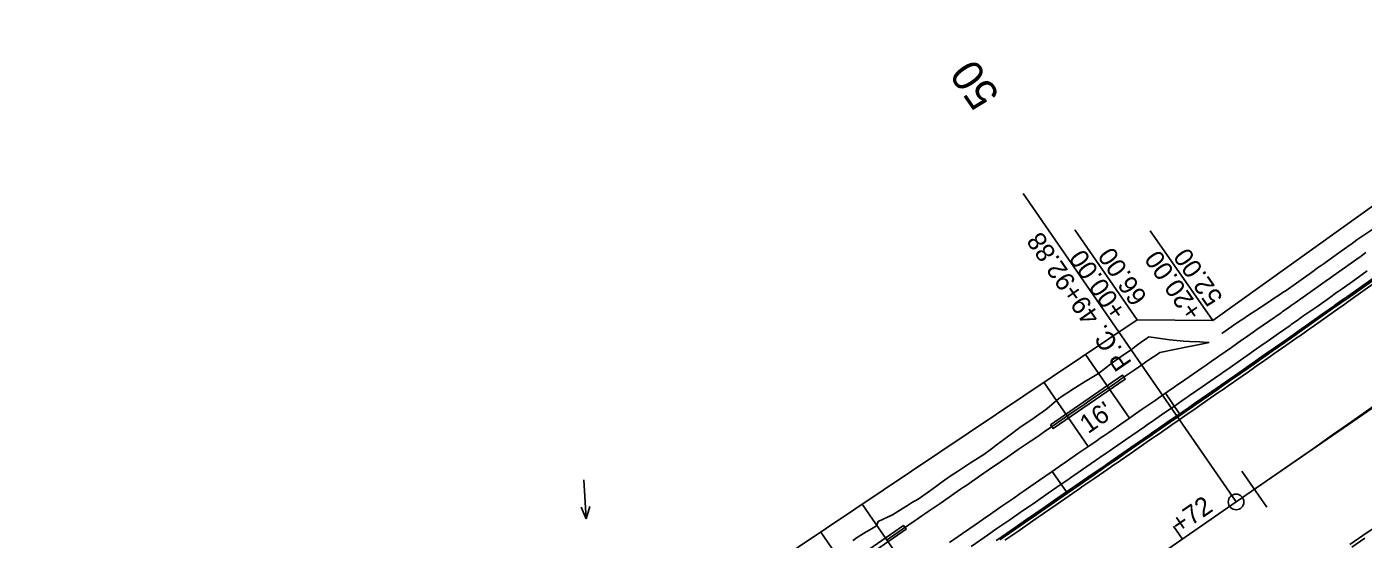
# Model space of a CAD drawing. Extents: x 1147550 to 1149124, y 2017436 to 2018779.
# Drawn here: x 1147906 to 1148333.9, y 2018014.6 to 2018178.7 of the extents above; entities that cross this region are included whole.
import ezdxf

# ---------------------------------------------------------------- set-up
doc = ezdxf.new("R2010")
doc.units = 0
for name, color, linetype in [('S_EDGE_CONCRETE', 7, 'Continuous'), ('S_ELECTRIC_UTILITIES', 7, 'Continuous'), ('S_HEADWALL', 7, 'Continuous'), ('S_MAILBOX', 7, 'Continuous'), ('S_RDW_PT_SYM', 7, 'Continuous'), ('S_SECONDARY_CTL', 7, 'Continuous'), ('S_TANK', 7, 'Continuous'), ('S_TELEPHONE_UTILITIES', 7, 'Continuous'), ('S_TELEPHONE_UTILITIES_ANNOT', 7, 'Continuous'), ('S_UTL_PT_SYM', 7, 'Continuous')]:
    doc.layers.add(name, color=color, linetype=linetype)

msp = doc.modelspace()

# ---------------------------------------------------------------- linework, layer by layer
at = {"layer": 'S_EDGE_CONCRETE'}
for p, q in [((1148293.22, 2018026.54), (1148491.47, 2018163.46)), ((1148208.89, 2017968.31), (1148293.22, 2018026.54))]:
    msp.add_line(p, q, dxfattribs=at)
msp.add_lwpolyline([(1148295.09, 2018036.35), (1148303.06, 2018024.84)], dxfattribs=at)
msp.add_circle((1148293.22, 2018026.54), 2.5, dxfattribs=at)
msp.add_arc((1145037.29, 2022741.09), 5729.58, 304.629463, 309.445337, dxfattribs=at)
at = {"layer": 'S_ELECTRIC_UTILITIES'}
for points in [[(1148261.5, 2018084.85), (1148241.57, 2018113.63)], [(1148285.74, 2018084.65), (1148265.72, 2018113.36)]]:
    msp.add_lwpolyline(points, dxfattribs=at)
at = {"layer": 'S_HEADWALL'}
for p, q in [((1148244.95, 2018073.76), (1148259.03, 2018053.37)), ((1148231.66, 2018064.85), (1148245.87, 2018044.28)), ((1148270.55, 2018061.33), (1148275.1, 2018054.74)), ((1148234.35, 2018036.32), (1148238.9, 2018029.74)), ((1148173.48, 2018025.83), (1148188.24, 2018004.48)), ((1148273.19, 2018018.79), (1148276.03, 2018014.68)), ((1148160.19, 2018016.91), (1148175.09, 2017995.38))]:
    msp.add_line(p, q, dxfattribs=at)
at = {"layer": 'S_MAILBOX'}
msp.add_lwpolyline([(1147550.1, 2017525.89), (1147894.72, 2017801.4), (1147903.55, 2017831.14), (1148035.64, 2017933.4), (1148261.5, 2018084.85), (1148285.74, 2018084.65), (1148479.1, 2018223.18), (1148835.76, 2018573.62)], dxfattribs=at)
at = {"layer": 'S_RDW_PT_SYM'}
msp.add_lwpolyline([(1148293.22, 2018026.54), (1148225.03, 2018125.28)], dxfattribs=at)
at = {"layer": 'S_SECONDARY_CTL'}
for points in [[(1148288.66, 2018080.48), (1148291.86, 2018082.74), (1148292.71, 2018083.33), (1148294.86, 2018084.79), (1148295.65, 2018085.31), (1148296.83, 2018086.09), (1148300.97, 2018088.83), (1148304.69, 2018091.27), (1148305.12, 2018091.55), (1148307.42, 2018093.06), (1148308.01, 2018093.44), (1148309.27, 2018094.27), (1148313.32, 2018097.14), (1148317.35, 2018100.03), (1148317.36, 2018100.04), (1148319.64, 2018101.67), (1148320.16, 2018102.05), (1148321.38, 2018102.92), (1148325.41, 2018105.8), (1148329.45, 2018108.68), (1148329.9, 2018109), (1148331.9, 2018110.42), (1148332.19, 2018110.63), (1148333.49, 2018111.55), (1148337.61, 2018114.33)], [(1148170.54, 2018014.23), (1148171.31, 2018014.76), (1148171.38, 2018014.8), (1148174.8, 2018016.96), (1148175.15, 2018017.17), (1148177.02, 2018018.29), (1148178.03, 2018018.92), (1148178.58, 2018020.29), (1148183.15, 2018022.47), (1148187.41, 2018025.09), (1148188.01, 2018025.46), (1148189.6, 2018026.44), (1148190.61, 2018027.06), (1148191.69, 2018027.7), (1148195.81, 2018030.54), (1148199.82, 2018033.53), (1148201.96, 2018034.99), (1148202.86, 2018035.6), (1148203.95, 2018036.34), (1148208.16, 2018039.04), (1148212.38, 2018041.74), (1148214.45, 2018043.25), (1148215.34, 2018043.9), (1148216.42, 2018044.69), (1148220.39, 2018047.74), (1148224.39, 2018050.75), (1148226.52, 2018052.13), (1148227.44, 2018052.74), (1148228.57, 2018053.49), (1148232.65, 2018056.37), (1148236.43, 2018059.71), (1148238.48, 2018061.06), (1148239.52, 2018061.72), (1148240.62, 2018062.44), (1148242.3, 2018063.52), (1148244.84, 2018065.12), (1148249.13, 2018067.71), (1148251.1, 2018069.15), (1148252.04, 2018069.94), (1148253.07, 2018070.81), (1148257.2, 2018073.63), (1148259.59, 2018075.23), (1148261.26, 2018076.5), (1148263.27, 2018077.99), (1148264.1, 2018078.59), (1148265.25, 2018079.44), (1148271.96, 2018078.44), (1148276.36, 2018078.05), (1148278.34, 2018077.94), (1148281.57, 2018077.77), (1148282.8, 2018077.71), (1148284.6, 2018077.62)]]:
    msp.add_lwpolyline(points, dxfattribs=at)
at = {"layer": 'S_TANK'}
for p, q in [((1148084.32, 2018033.67), (1148085.13, 2018021.13)), ((1148085.13, 2018021.13), (1148083.49, 2018024.88)), ((1148085.13, 2018021.13), (1148086.28, 2018025.06))]:
    msp.add_line(p, q, dxfattribs=at)
at = {"layer": 'S_TELEPHONE_UTILITIES'}
for points in [[(1148201.44, 2018013.59), (1148205.55, 2018016.43), (1148209.66, 2018019.27), (1148211.79, 2018020.75), (1148212.69, 2018021.37), (1148213.78, 2018022.12), (1148217.89, 2018024.96), (1148222.01, 2018027.8), (1148224.12, 2018029.26), (1148225.02, 2018029.88), (1148226.12, 2018030.64), (1148230.24, 2018033.48), (1148234.35, 2018036.32), (1148236.44, 2018037.77), (1148237.35, 2018038.39), (1148238.46, 2018039.16), (1148242.58, 2018042.01), (1148246.69, 2018044.85), (1148248.72, 2018046.24), (1148249.72, 2018046.94), (1148250.81, 2018047.69), (1148252.45, 2018048.82), (1148254.92, 2018050.53), (1148259.03, 2018053.37), (1148261.04, 2018054.76), (1148262.05, 2018055.45), (1148263.15, 2018056.21), (1148267.26, 2018059.05), (1148269.64, 2018060.69), (1148271.36, 2018061.89), (1148273.43, 2018063.31), (1148274.27, 2018063.89), (1148275.45, 2018064.71), (1148279.53, 2018067.54), (1148282.31, 2018069.47), (1148283.6, 2018070.37), (1148285.7, 2018071.83), (1148286.5, 2018072.39), (1148287.68, 2018073.2), (1148291.75, 2018076.04), (1148294.97, 2018078.29), (1148295.82, 2018078.88), (1148297.95, 2018080.37), (1148298.72, 2018080.92), (1148299.89, 2018081.73), (1148303.95, 2018084.58), (1148307.6, 2018087.14), (1148308.01, 2018087.43), (1148310.27, 2018089.02), (1148310.84, 2018089.42), (1148312.07, 2018090.29), (1148316.13, 2018093.15), (1148320.19, 2018096.01), (1148320.21, 2018096.02), (1148322.49, 2018097.64), (1148323.02, 2018098.01), (1148324.24, 2018098.88), (1148328.29, 2018101.75), (1148332.34, 2018104.62), (1148332.79, 2018104.94), (1148334.79, 2018106.36)], [(1148208.39, 2018012.32), (1148212.51, 2018015.16), (1148214.64, 2018016.63), (1148215.53, 2018017.25), (1148216.62, 2018018), (1148220.73, 2018020.84), (1148224.85, 2018023.68), (1148226.96, 2018025.14), (1148227.86, 2018025.76), (1148228.96, 2018026.53), (1148233.08, 2018029.37), (1148237.19, 2018032.21), (1148239.28, 2018033.65), (1148240.19, 2018034.28), (1148241.3, 2018035.05), (1148245.42, 2018037.89), (1148249.53, 2018040.73), (1148251.56, 2018042.13), (1148252.57, 2018042.83), (1148253.65, 2018043.57), (1148255.29, 2018044.71), (1148257.76, 2018046.41), (1148261.88, 2018049.26), (1148263.88, 2018050.64), (1148264.89, 2018051.34), (1148265.99, 2018052.1), (1148270.1, 2018054.94), (1148272.48, 2018056.58), (1148274.21, 2018057.77), (1148276.27, 2018059.2), (1148277.11, 2018059.78), (1148278.29, 2018060.6), (1148282.38, 2018063.43), (1148285.17, 2018065.37), (1148286.46, 2018066.26), (1148288.56, 2018067.72), (1148289.36, 2018068.28), (1148290.54, 2018069.1), (1148294.61, 2018071.94), (1148297.83, 2018074.19), (1148298.68, 2018074.79), (1148300.82, 2018076.28), (1148301.59, 2018076.82), (1148302.76, 2018077.63), (1148306.82, 2018080.48), (1148310.47, 2018083.05), (1148310.89, 2018083.34), (1148313.15, 2018084.93), (1148313.72, 2018085.33), (1148314.95, 2018086.2), (1148319.01, 2018089.06), (1148323.07, 2018091.93), (1148323.09, 2018091.94), (1148325.38, 2018093.56), (1148325.91, 2018093.93), (1148327.13, 2018094.8), (1148331.18, 2018097.67), (1148335.23, 2018100.54)], [(1148216.34, 2018014.16), (1148217.24, 2018014.78), (1148218.32, 2018015.53), (1148222.44, 2018018.37), (1148226.55, 2018021.22), (1148228.66, 2018022.67), (1148229.56, 2018023.29), (1148230.67, 2018024.06), (1148234.78, 2018026.9), (1148238.9, 2018029.74), (1148240.98, 2018031.18), (1148241.89, 2018031.81), (1148243.01, 2018032.58), (1148247.12, 2018035.42), (1148251.24, 2018038.26), (1148253.26, 2018039.66), (1148254.27, 2018040.36), (1148255.35, 2018041.1), (1148257, 2018042.24), (1148259.47, 2018043.95), (1148263.58, 2018046.79), (1148265.59, 2018048.17), (1148266.59, 2018048.87), (1148267.69, 2018049.63), (1148271.81, 2018052.47), (1148274.18, 2018054.11), (1148275.91, 2018055.3), (1148277.98, 2018056.73), (1148278.82, 2018057.32), (1148280, 2018058.13), (1148284.09, 2018060.96), (1148286.88, 2018062.9), (1148288.17, 2018063.8), (1148290.27, 2018065.26), (1148291.07, 2018065.82), (1148292.25, 2018066.64), (1148296.33, 2018069.48), (1148299.55, 2018071.73), (1148300.4, 2018072.33), (1148302.54, 2018073.82), (1148303.31, 2018074.36), (1148304.48, 2018075.18), (1148308.55, 2018078.03), (1148312.2, 2018080.59), (1148312.61, 2018080.89), (1148314.87, 2018082.47), (1148315.44, 2018082.87), (1148316.68, 2018083.75), (1148320.74, 2018086.61), (1148324.8, 2018089.48), (1148324.82, 2018089.49), (1148327.11, 2018091.11), (1148327.64, 2018091.48), (1148328.86, 2018092.35), (1148332.92, 2018095.22), (1148336.97, 2018098.1)], [(1148217.52, 2018014.37), (1148218.61, 2018015.12), (1148222.72, 2018017.96), (1148226.84, 2018020.8), (1148228.95, 2018022.26), (1148229.85, 2018022.88), (1148230.95, 2018023.65), (1148235.07, 2018026.49), (1148239.18, 2018029.33), (1148241.27, 2018030.77), (1148242.18, 2018031.4), (1148243.29, 2018032.17), (1148247.41, 2018035.01), (1148251.52, 2018037.85), (1148253.55, 2018039.25), (1148254.55, 2018039.95), (1148255.64, 2018040.69), (1148257.28, 2018041.83), (1148259.75, 2018043.53), (1148263.86, 2018046.38), (1148265.87, 2018047.76), (1148266.88, 2018048.46), (1148267.98, 2018049.22), (1148272.09, 2018052.06), (1148274.47, 2018053.7), (1148276.2, 2018054.89), (1148278.26, 2018056.32), (1148279.11, 2018056.91), (1148280.29, 2018057.72), (1148284.37, 2018060.55), (1148287.16, 2018062.49), (1148288.45, 2018063.39), (1148290.56, 2018064.85), (1148291.36, 2018065.41), (1148292.54, 2018066.23), (1148296.61, 2018069.07), (1148299.84, 2018071.32), (1148300.69, 2018071.92), (1148302.83, 2018073.41), (1148303.6, 2018073.95), (1148304.76, 2018074.77), (1148308.83, 2018077.62), (1148312.49, 2018080.18), (1148312.9, 2018080.48), (1148315.16, 2018082.06), (1148315.73, 2018082.47), (1148316.97, 2018083.34), (1148321.03, 2018086.2), (1148325.09, 2018089.07), (1148325.11, 2018089.08), (1148327.4, 2018090.7), (1148327.93, 2018091.07), (1148329.15, 2018091.94), (1148333.21, 2018094.81), (1148337.26, 2018097.69)], [(1148219.18, 2018014.3), (1148223.29, 2018017.14), (1148227.41, 2018019.98), (1148229.52, 2018021.44), (1148230.42, 2018022.06), (1148231.52, 2018022.82), (1148235.63, 2018025.66), (1148239.75, 2018028.51), (1148241.84, 2018029.95), (1148242.75, 2018030.58), (1148243.86, 2018031.35), (1148247.98, 2018034.19), (1148252.09, 2018037.03), (1148254.11, 2018038.43), (1148255.12, 2018039.12), (1148256.2, 2018039.87), (1148257.85, 2018041.01), (1148260.32, 2018042.71), (1148264.43, 2018045.55), (1148266.44, 2018046.94), (1148267.44, 2018047.63), (1148268.55, 2018048.39), (1148272.66, 2018051.24), (1148275.03, 2018052.87), (1148276.77, 2018054.07), (1148278.83, 2018055.5), (1148279.68, 2018056.08), (1148280.85, 2018056.9), (1148284.94, 2018059.73), (1148287.73, 2018061.67), (1148289.03, 2018062.57), (1148291.13, 2018064.03), (1148291.93, 2018064.59), (1148293.11, 2018065.41), (1148297.19, 2018068.25), (1148300.41, 2018070.5), (1148301.26, 2018071.1), (1148303.4, 2018072.59), (1148304.17, 2018073.13), (1148305.34, 2018073.95), (1148309.41, 2018076.8), (1148313.06, 2018079.37), (1148313.48, 2018079.66), (1148315.74, 2018081.25), (1148316.31, 2018081.65), (1148317.54, 2018082.52), (1148321.61, 2018085.38), (1148325.67, 2018088.25), (1148325.69, 2018088.26), (1148327.98, 2018089.89), (1148328.51, 2018090.26), (1148329.73, 2018091.12), (1148333.79, 2018094), (1148337.84, 2018096.88)], [(1148329.68, 2018012.89), (1148333.8, 2018015.76), (1148337.06, 2018018.04)], [(1148330.25, 2018012.07), (1148334.38, 2018014.94)]]:
    msp.add_lwpolyline(points, dxfattribs=at)
at = {"layer": 'S_TELEPHONE_UTILITIES_ANNOT'}
for points in [[(1148233.76, 2018051.26), (1148256.84, 2018067.11), (1148257.69, 2018065.87), (1148234.61, 2018050.02)], [(1148162.02, 2018001.97), (1148186.69, 2018019.03), (1148187.54, 2018017.8), (1148162.87, 2018000.73)]]:
    msp.add_lwpolyline(points, close=True, dxfattribs=at)
at = {"layer": 'S_UTL_PT_SYM'}
msp.add_lwpolyline([(1148181.22, 2018014.3), (1148182.23, 2018015), (1148186.36, 2018017.83), (1148190.48, 2018020.66), (1148191.06, 2018021.05), (1148192.59, 2018022.11), (1148193.57, 2018022.78), (1148194.6, 2018023.49), (1148198.73, 2018026.31), (1148202.85, 2018029.14), (1148204.98, 2018030.61), (1148205.88, 2018031.23), (1148206.97, 2018031.97), (1148211.09, 2018034.8), (1148215.22, 2018037.63), (1148217.33, 2018039.08), (1148218.23, 2018039.7), (1148219.34, 2018040.46), (1148223.46, 2018043.29), (1148227.58, 2018046.12), (1148229.68, 2018047.55), (1148230.59, 2018048.18), (1148231.71, 2018048.95), (1148235.83, 2018051.78), (1148239.95, 2018054.6), (1148241.98, 2018056), (1148242.99, 2018056.69), (1148244.08, 2018057.43), (1148245.72, 2018058.57), (1148248.2, 2018060.26), (1148252.32, 2018063.09), (1148254.33, 2018064.47), (1148255.34, 2018065.16), (1148256.44, 2018065.92), (1148260.57, 2018068.75), (1148262.94, 2018070.38), (1148264.67, 2018071.57), (1148266.73, 2018072.98), (1148267.58, 2018073.56), (1148268.76, 2018074.37), (1148274.03, 2018075.46), (1148277.64, 2018076.2), (1148279.31, 2018076.54), (1148282.04, 2018077.1), (1148283.08, 2018077.31), (1148284.6, 2018077.62)], dxfattribs=at)

# ---------------------------------------------------------------- texts
at = {"layer": 'S_ELECTRIC_UTILITIES'}
for s, rotation, p in [('+00.00', 124.7006, (1148258.4, 2018087.57)), ('66.00', 124.7006, (1148264.98, 2018092.13)), ('+20.00', 124.9006, (1148282.63, 2018087.36)), ('52.00', 124.9006, (1148289.2, 2018091.94))]:
    msp.add_text(s, height=6, rotation=rotation, dxfattribs=at).set_placement(p)
at = {"layer": 'S_HEADWALL'}
for s, p in [("16'", (1148245.81, 2018048.21)), ('+72', (1148275.01, 2018016.16))]:
    msp.add_text(s, height=6, rotation=34.6295, dxfattribs=at).set_placement(p)
at = {"layer": 'S_RDW_PT_SYM'}
for s, height, rotation, p in [('50', 10, 124.7006, (1148217.79, 2018156.76)), ('P.C. 49+92.88', 6, 124.6295, (1148260.01, 2018071.11))]:
    msp.add_text(s, height=height, rotation=rotation, dxfattribs=at).set_placement(p)

doc.saveas('drawing.dxf')
